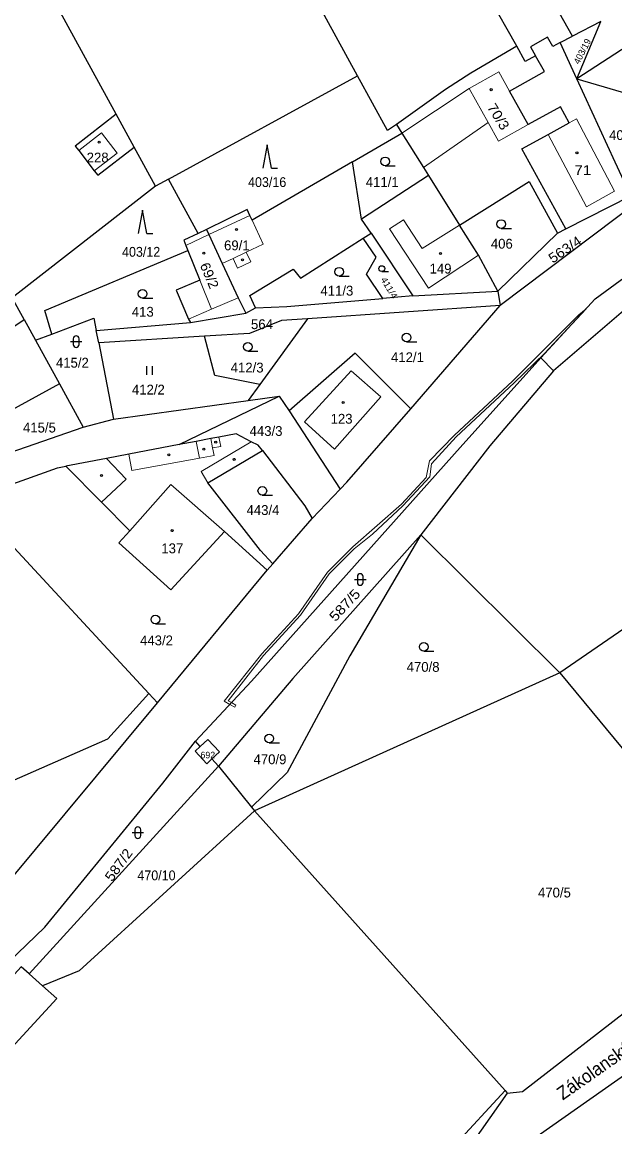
# Model space of a CAD drawing. Extents: x -754445 to -751443, y -1030748 to -1028224.
# Drawn here: x -753390.6 to -753288.1, y -1029073.5 to -1028882.4 of the extents above; entities that cross this region are included whole.
import ezdxf
from ezdxf.enums import TextEntityAlignment as Align

# ---------------------------------------------------------------- set-up
doc = ezdxf.new("R2010")
doc.units = 0
doc.header["$LTSCALE"] = 0.68
for name, color, linetype, lineweight in [('1', 7, 'Continuous', 25), ('13', 7, 'Continuous', 13), ('3', 7, 'Continuous', 25), ('4', 7, 'Continuous', 13), ('5', 7, 'Continuous', 25), ('7', 7, 'Continuous', 13)]:
    doc.layers.add(name, color=color, linetype=linetype, lineweight=lineweight)
doc.layers.add('2', color=7, linetype='Continuous')

msp = doc.modelspace()

# ---------------------------------------------------------------- linework, layer by layer
at = {"layer": '1'}
for p, q in [((-753305.08, -1028886.55), (-753326.53, -1028848.47)), ((-753365.3, -1028909.56), (-753332.6, -1028891.68)), ((-753371.22, -1028904), (-753374.33, -1028898.31)), ((-753333.5, -1028906.55), (-753324.95, -1028901.58)), ((-753367.52, -1028910.77), (-753371.22, -1028904)), ((-753320.35, -1028908.9), (-753331.91, -1028916.46)), ((-753358.73, -1028918.22), (-753360.18, -1028918.92)), ((-753308.36, -1028928.92), (-753298.03, -1028918.88)), ((-753390.28, -1028933.79), (-753392.33, -1028930.04)), ((-753323.03, -1028929.71), (-753328.26, -1028930.16)), ((-753308.36, -1028928.92), (-753307.94, -1028931.4)), ((-753377.78, -1028935.73), (-753361.49, -1028934.35)), ((-753377.37, -1028937.83), (-753377.78, -1028935.73)), ((-753300.94, -1028940.42), (-753298.71, -1028942.67)), ((-753384.17, -1028944.96), (-753401.72, -1028954.55)), ((-753363.45, -1028955.45), (-753346.15, -1028947.05)), ((-753380.08, -1028952.45), (-753374.79, -1028951.05)), ((-753344.46, -1028949.64), (-753335.62, -1028963.18)), ((-753347.27, -1028976.07), (-753340.47, -1028968.21)), ((-753321.68, -1028971.05), (-753297.62, -1028994.95)), ((-753297.62, -1028994.95), (-753350.45, -1029018.81)), ((-753356.65, -1029011.07), (-753357.8, -1029009.83)), ((-753356.65, -1029011.07), (-753389.38, -1029047.03)), ((-753356.65, -1029011.07), (-753350.96, -1029018.18)), ((-753387.07, -1029049.07), (-753389.38, -1029047.03)), ((-753307.09, -1029067.21), (-753306.72, -1029067.62))]:
    msp.add_line(p, q, dxfattribs=at)
for points in [[(-753332.6, -1028891.68), (-753349.38, -1028860.96), (-753357.68, -1028845.79), (-753366.13, -1028830.34)], [(-753297.57, -1028885.92), (-753295.46, -1028884.79), (-753318.45, -1028844.06), (-753326.53, -1028848.47)], [(-753374.33, -1028898.31), (-753392.6, -1028864.88), (-753403, -1028845.85)], [(-753294.67, -1028892.21), (-753290.53, -1028882.28), (-753295.46, -1028884.79)], [(-753281.53, -1028883.63), (-753294.67, -1028892.21), (-753262.81, -1028901.51)], [(-753305.08, -1028886.55), (-753313, -1028891.22), (-753317.41, -1028894.03), (-753325.9, -1028900.07), (-753324.95, -1028901.58)], [(-753301.83, -1028888.21), (-753303.61, -1028889.16), (-753305.08, -1028886.55)], [(-753297.57, -1028885.92), (-753298.85, -1028886.61), (-753299.76, -1028884.99), (-753302.71, -1028886.65), (-753301.83, -1028888.21)], [(-753288.04, -1028906.61), (-753294.67, -1028892.21), (-753297.57, -1028885.92)], [(-753296.61, -1028918.16), (-753304.19, -1028904.29), (-753299.62, -1028901.79), (-753296, -1028899.82), (-753297.54, -1028897), (-753303.08, -1028900.11), (-753306.33, -1028894.31), (-753300.29, -1028890.92), (-753301.83, -1028888.21)], [(-753325.9, -1028900.07), (-753327.42, -1028901.15), (-753332.6, -1028891.68)], [(-753245.48, -1028897.41), (-753261.79, -1028902.68), (-753275.92, -1028908.54), (-753283.86, -1028913.22), (-753307.94, -1028931.4)], [(-753374.33, -1028898.31), (-753381.43, -1028903.81), (-753380.82, -1028904.6), (-753378.13, -1028908.08), (-753377.52, -1028908.87), (-753371.22, -1028904)], [(-753324.95, -1028901.58), (-753321.22, -1028907.51), (-753320.35, -1028908.9), (-753314.95, -1028917.5)], [(-753333.5, -1028906.55), (-753350.85, -1028916.63), (-753351.24, -1028915.81), (-753351.71, -1028914.81), (-753358.73, -1028918.22)], [(-753331.63, -1028919.75), (-753330.28, -1028918.89), (-753331.91, -1028916.46), (-753333.5, -1028906.55)], [(-753296.61, -1028918.16), (-753285.35, -1028912.45), (-753288.04, -1028906.61)], [(-753360.18, -1028918.92), (-753365.3, -1028909.56), (-753367.52, -1028910.77), (-753392.33, -1028930.04)], [(-753314.95, -1028917.5), (-753302.91, -1028909.94), (-753298.03, -1028918.88), (-753296.61, -1028918.16)], [(-753360.18, -1028918.92), (-753362.67, -1028920.12), (-753362.31, -1028921.01), (-753361.96, -1028921.89)], [(-753358.73, -1028918.22), (-753358.31, -1028919.13), (-753356.01, -1028924.13), (-753353.28, -1028930.04), (-753351.91, -1028932.7), (-753350.24, -1028931.79)], [(-753330.28, -1028918.89), (-753323.03, -1028929.71), (-753308.36, -1028928.92)], [(-753308.36, -1028928.92), (-753311.68, -1028922.71), (-753314.95, -1028917.5)], [(-753350.24, -1028931.79), (-753351.21, -1028929.64), (-753343.72, -1028925.08), (-753342.46, -1028926.68), (-753331.63, -1028919.75)], [(-753350.24, -1028931.79), (-753344.82, -1028931.58), (-753328.26, -1028930.16), (-753331.07, -1028925.98), (-753329.41, -1028923.06), (-753331.63, -1028919.75)], [(-753233.79, -1028923.65), (-753232.06, -1028922.2), (-753233.74, -1028920.02), (-753236.01, -1028919.42), (-753256.01, -1028920.74), (-753278.94, -1028925.76), (-753298.71, -1028942.67)], [(-753385.5, -1028936.34), (-753386.69, -1028932.27), (-753361.96, -1028921.89)], [(-753361.96, -1028921.89), (-753359.9, -1028926.99), (-753363.98, -1028928.76), (-753361.83, -1028933.73), (-753361.49, -1028934.35), (-753351.91, -1028932.7)], [(-753300.94, -1028940.42), (-753291.49, -1028930.23), (-753282.22, -1028923.45)], [(-753323.4, -1028949.26), (-753307.94, -1028931.4), (-753341.29, -1028933.71), (-753349.53, -1028945.03), (-753351.55, -1028947.8), (-753346.15, -1028947.05), (-753344.46, -1028949.64)], [(-753408.77, -1028941.67), (-753399.03, -1028939.66), (-753390.28, -1028933.79)], [(-753390.28, -1028933.79), (-753388.3, -1028937.41), (-753385.5, -1028936.34)], [(-753385.5, -1028936.34), (-753378.2, -1028933.56), (-753377.78, -1028935.73)], [(-753341.29, -1028933.71), (-753345.74, -1028933.98), (-753351.27, -1028936.21), (-753359.09, -1028936.69)], [(-753388.3, -1028937.41), (-753384.17, -1028944.96), (-753380.08, -1028952.45)], [(-753349.53, -1028945.03), (-753357.28, -1028943.5), (-753359.09, -1028936.69), (-753377.37, -1028937.83)], [(-753377.37, -1028937.83), (-753374.79, -1028951.05), (-753351.55, -1028947.8)], [(-753323.4, -1028949.26), (-753333.03, -1028939.62), (-753344.46, -1028949.64)], [(-753360.62, -1029006.78), (-753350.96, -1028996.35), (-753314.84, -1028955.94), (-753300.94, -1028940.42)], [(-753298.71, -1028942.67), (-753309.75, -1028955.64), (-753321.68, -1028971.05)], [(-753335.62, -1028963.18), (-753334.45, -1028961.96), (-753323.4, -1028949.26)], [(-753464.67, -1028987.34), (-753448.8, -1028985.04), (-753428.33, -1028974.85), (-753396.89, -1028958.28), (-753380.08, -1028952.45)], [(-753349.07, -1028956.49), (-753349.78, -1028955.57), (-753350.98, -1028954.95), (-753353.6, -1028953.6), (-753356.57, -1028954.15), (-753357.99, -1028954.41), (-753360.49, -1028954.89), (-753363.45, -1028955.45)], [(-753363.45, -1028955.45), (-753372.13, -1028957.11), (-753376.03, -1028957.85), (-753383.05, -1028959.19)], [(-753347.27, -1028976.07), (-753349.37, -1028973.79), (-753358.5, -1028962.06), (-753349.07, -1028956.49)], [(-753349.07, -1028956.49), (-753341.72, -1028966.04), (-753340.47, -1028968.21), (-753335.62, -1028963.18)], [(-753394.88, -1028970.27), (-753399.83, -1028964.93), (-753384.52, -1028959.47), (-753383.05, -1028959.19)], [(-753383.05, -1028959.19), (-753376.87, -1028965.44), (-753372.01, -1028970.35), (-753373.87, -1028972.44), (-753364.88, -1028980.58), (-753355.61, -1028970.46), (-753348.23, -1028977.18), (-753347.27, -1028976.07)], [(-753400.1, -1029017), (-753375.78, -1029006.35), (-753368.71, -1028998.51), (-753394.88, -1028970.27)], [(-753321.68, -1028971.05), (-753343.79, -1028995.9), (-753356.65, -1029011.07)], [(-753321.68, -1028971.05), (-753333.97, -1028991.99), (-753344.8, -1029012.18), (-753350.96, -1029018.18), (-753350.45, -1029018.81)], [(-753368.71, -1028998.51), (-753367.2, -1029000.13), (-753348.23, -1028977.18)], [(-753282.89, -1028984.8), (-753297.62, -1028994.95), (-753266.4, -1029032.68)], [(-753419.48, -1029055.17), (-753408.84, -1029042.69), (-753393.71, -1029032.01), (-753367.2, -1029000.13)], [(-753429.75, -1029105.16), (-753421.74, -1029083.85), (-753416.16, -1029071.29), (-753408.48, -1029060.98), (-753399.35, -1029051.11), (-753386.69, -1029038.91), (-753366.27, -1029014.04), (-753360.62, -1029006.78)], [(-753357.8, -1029009.83), (-753358.69, -1029010.65), (-753360.69, -1029008.48), (-753359.8, -1029007.66), (-753360.62, -1029006.78)], [(-753357.8, -1029009.83), (-753356.48, -1029008.62), (-753358.48, -1029006.45), (-753359.8, -1029007.66)], [(-753350.45, -1029018.81), (-753380.72, -1029046.48), (-753387.07, -1029049.07)], [(-753369.62, -1029134.97), (-753307.09, -1029067.21), (-753350.45, -1029018.81)], [(-753239.27, -1029023.03), (-753276.34, -1029057.44), (-753301.53, -1029075.12), (-753321.63, -1029103.19)], [(-753306.72, -1029067.62), (-753304.1, -1029067.37), (-753283.84, -1029051.7), (-753266.4, -1029032.68)], [(-753389.38, -1029047.03), (-753390.8, -1029045.77), (-753407.74, -1029064.38), (-753407.08, -1029064.97)], [(-753387.07, -1029049.07), (-753384.63, -1029051.28), (-753401.69, -1029069.8), (-753407.08, -1029064.97)], [(-753306.72, -1029067.62), (-753331.11, -1029102.37), (-753369.62, -1029134.97)]]:
    msp.add_lwpolyline(points, dxfattribs=at)
at = {"layer": '13'}
for points in [[(-753355.67, -1028999.83), (-753354.7, -1029000.39), (-753354.43, -1029000.09), (-753354.98, -1028999.77), (-753348.85, -1028991.93), (-753342.5, -1028984.97), (-753337.52, -1028977.79), (-753333.18, -1028973.46), (-753330.03, -1028970.93), (-753324.75, -1028966.02), (-753320.12, -1028961.03), (-753319.82, -1028958.78), (-753315.55, -1028954.13), (-753305.52, -1028944.75), (-753300.26, -1028939.69), (-753293.09, -1028931.96), (-753294.36, -1028933), (-753305.8, -1028944.47), (-753315.83, -1028953.85), (-753320.16, -1028958.29), (-753320.77, -1028961.14), (-753325.03, -1028965.74), (-753333.44, -1028973.16), (-753337.82, -1028977.53), (-753342.82, -1028984.73), (-753349.15, -1028991.67)], [(-753353.65, -1029000.54), (-753354.43, -1029000.09), (-753354.7, -1029000.39), (-753353.84, -1029000.89)]]:
    msp.add_lwpolyline(points, close=True, dxfattribs=at)
at = {"layer": '3'}
for p, q in [((-753327.833, -1028907.21), (-753326.083, -1028907.21)), ((-753347.46, -1028907.61), (-753346.464, -1028907.61)), ((-753369.03, -1028918.93), (-753368.034, -1028918.93)), ((-753307.763, -1028918.05), (-753306.013, -1028918.05)), ((-753335.793, -1028926.3), (-753334.043, -1028926.3)), ((-753328.415, -1028925.52), (-753327.243, -1028925.52)), ((-753369.773, -1028930.11), (-753368.023, -1028930.11)), ((-753382.271, -1028937.631), (-753380.269, -1028937.631)), ((-753381.771, -1028937.131), (-753381.771, -1028938.132)), ((-753380.769, -1028938.132), (-753380.769, -1028937.131)), ((-753324.123, -1028937.67), (-753322.373, -1028937.67)), ((-753351.593, -1028939.29), (-753349.843, -1028939.29)), ((-753369.041, -1028943.38), (-753369.041, -1028941.88)), ((-753368.04, -1028943.38), (-753368.04, -1028941.88)), ((-753349.073, -1028964.2), (-753347.323, -1028964.2)), ((-753333.141, -1028978.791), (-753331.139, -1028978.791)), ((-753332.641, -1028978.291), (-753332.641, -1028979.292)), ((-753331.639, -1028979.292), (-753331.639, -1028978.291)), ((-753367.573, -1028986.47), (-753365.823, -1028986.47)), ((-753321.163, -1028991.2), (-753319.413, -1028991.2)), ((-753347.873, -1029007.05), (-753346.123, -1029007.05)), ((-753371.101, -1029022.081), (-753371.101, -1029023.082)), ((-753370.099, -1029023.082), (-753370.099, -1029022.081)), ((-753371.601, -1029022.581), (-753369.599, -1029022.581))]:
    msp.add_line(p, q, dxfattribs=at)
for points in [[(-753347.46, -1028907.61), (-753348.21, -1028903.61), (-753348.96, -1028907.61)], [(-753369.03, -1028918.93), (-753369.78, -1028914.93), (-753370.53, -1028918.93)]]:
    msp.add_lwpolyline(points, dxfattribs=at)
for centre, radius in [((-753327.8329, -1028906.4598), 0.75), ((-753307.7629, -1028917.2998), 0.75), ((-753328.4152, -1028925.0174), 0.5025), ((-753335.7929, -1028925.5498), 0.75), ((-753369.7729, -1028929.3598), 0.75), ((-753324.1229, -1028936.9198), 0.75), ((-753351.5929, -1028938.5398), 0.75), ((-753349.0729, -1028963.4498), 0.75), ((-753367.5729, -1028985.7198), 0.75), ((-753321.1629, -1028990.4498), 0.75), ((-753347.8729, -1029006.2998), 0.75)]:
    msp.add_circle(centre, radius, dxfattribs=at)
for centre, start, end in [((-753381.27, -1028937.1309), 0, 180), ((-753381.27, -1028938.1309), 180, 359.98789), ((-753332.14, -1028978.2909), 0, 180), ((-753332.14, -1028979.2909), 180, 359.98789), ((-753370.6, -1029022.0809), 0, 180), ((-753370.6, -1029023.0809), 180, 359.98789)]:
    msp.add_arc(centre, 0.5, start, end, dxfattribs=at)
at = {"layer": '4'}
for p, q in [((-753308.19, -1028890.99), (-753313.33, -1028893.87)), ((-753308.19, -1028890.99), (-753306.33, -1028894.31)), ((-753313.33, -1028893.87), (-753324.95, -1028901.58)), ((-753313.33, -1028893.87), (-753310.03, -1028899.76)), ((-753310.03, -1028899.76), (-753321.22, -1028907.51)), ((-753310.03, -1028899.76), (-753308.22, -1028902.99)), ((-753296, -1028899.82), (-753294.75, -1028899.13)), ((-753294.75, -1028899.13), (-753288.17, -1028911.64)), ((-753380.82, -1028904.6), (-753376.87, -1028901.54)), ((-753374.18, -1028905.02), (-753376.87, -1028901.54)), ((-753308.22, -1028902.99), (-753303.08, -1028900.11)), ((-753299.62, -1028901.79), (-753293.04, -1028914.3)), ((-753378.13, -1028908.08), (-753374.18, -1028905.02)), ((-753293.04, -1028914.3), (-753288.17, -1028911.64)), ((-753358.31, -1028919.13), (-753351.24, -1028915.81)), ((-753350.85, -1028916.63), (-753348.9, -1028920.79)), ((-753324.68, -1028916.58), (-753327.07, -1028918.14)), ((-753321.42, -1028921.56), (-753324.68, -1028916.58)), ((-753327.07, -1028918.14), (-753320.36, -1028928.39)), ((-753321.42, -1028921.56), (-753314.95, -1028917.5)), ((-753362.31, -1028921.01), (-753358.31, -1028919.13)), ((-753348.9, -1028920.79), (-753351.84, -1028922.17)), ((-753351.84, -1028922.17), (-753354.14, -1028923.25)), ((-753351.84, -1028922.17), (-753351.05, -1028923.85)), ((-753320.36, -1028928.39), (-753311.68, -1028922.71)), ((-753354.14, -1028923.25), (-753356.01, -1028924.13)), ((-753354.14, -1028923.25), (-753353.36, -1028924.91)), ((-753351.05, -1028923.85), (-753353.36, -1028924.91)), ((-753357.87, -1028932.02), (-753359.9, -1028926.99)), ((-753357.87, -1028932.02), (-753353.28, -1028930.04)), ((-753361.83, -1028933.73), (-753357.87, -1028932.02)), ((-753333.7, -1028942.67), (-753341.78, -1028951.49)), ((-753333.7, -1028942.67), (-753328.6, -1028947.19)), ((-753328.6, -1028947.19), (-753336.61, -1028956.23)), ((-753336.61, -1028956.23), (-753341.78, -1028951.49)), ((-753359.93, -1028957.81), (-753360.49, -1028954.89)), ((-753359.67, -1028960.08), (-753350.98, -1028954.95)), ((-753357.68, -1028956.03), (-753357.99, -1028954.41)), ((-753356.27, -1028955.77), (-753356.57, -1028954.15)), ((-753372.13, -1028957.11), (-753371.62, -1028959.93)), ((-753357.68, -1028956.03), (-753356.27, -1028955.77)), ((-753357.43, -1028957.36), (-753357.68, -1028956.03)), ((-753376.03, -1028957.85), (-753372.64, -1028961.41)), ((-753371.62, -1028959.93), (-753359.93, -1028957.81)), ((-753359.93, -1028957.81), (-753357.43, -1028957.36)), ((-753358.5, -1028962.06), (-753359.67, -1028960.08)), ((-753376.87, -1028965.44), (-753372.64, -1028961.41)), ((-753372.01, -1028970.35), (-753364.89, -1028962.33)), ((-753364.89, -1028962.33), (-753355.61, -1028970.46))]:
    msp.add_line(p, q, dxfattribs=at)
at = {"layer": '5'}
for centre in [(-753309.5068, -1028894.0592), (-753377.3068, -1028903.1292), (-753294.6668, -1028904.9992), (-753353.5368, -1028918.2592), (-753359.1768, -1028922.3392), (-753318.2668, -1028922.3892), (-753352.5068, -1028923.4992), (-753335.0968, -1028948.1892), (-753357.1368, -1028955.0492), (-753365.2468, -1028957.2092), (-753359.1868, -1028956.2392), (-753353.9468, -1028958.0092), (-753376.8668, -1028960.7992), (-753364.6468, -1028970.3392)]:
    msp.add_circle(centre, 0.175, dxfattribs=at)

# ---------------------------------------------------------------- texts
at = {"layer": '2'}
msp.add_text('403/19', height=1.14, rotation=63, dxfattribs=at).set_placement((-753293.2437, -1028887.6853), align=Align.CENTER)
for s, height, rotation, width, p in [('70/3', 1.7, 302, 1.1, (-753308.9726, -1028899.1701)), ('563/4', 1.7, 34, 1.1, (-753296.2668, -1028922.4104)), ('69/2', 1.7, 293, 1.05, (-753359.0083, -1028926.5534)), ('411/4', 1.14, 301, 1.05, (-753327.6105, -1028928.6289)), ('587/5', 1.7, 47, 1.15, (-753334.2072, -1028983.8032)), ('587/2', 1.7, 54, 1.1, (-753373.2301, -1029028.6566))]:
    msp.add_text(s, height=height, rotation=rotation, dxfattribs=dict(at, width=width)).set_placement(p, align=Align.CENTER)
for s, height, p in [('402/2', 1.7, (-753286.26, -1028902.77)), ('228', 1.7, (-753377.549, -1028906.65)), ('411/1', 1.7, (-753328.34, -1028910.89)), ('69/1', 1.7, (-753353.48, -1028921.84)), ('406', 1.7, (-753307.659, -1028921.56)), ('149', 1.7, (-753318.259, -1028925.86)), ('411/3', 1.7, (-753336.18, -1028929.68)), ('413', 1.7, (-753369.749, -1028933.33)), ('564', 1.7, (-753349.139, -1028935.48)), ('412/1', 1.7, (-753323.98, -1028941.19)), ('415/2', 1.7, (-753381.92, -1028942.14)), ('412/3', 1.7, (-753351.7, -1028942.98)), ('412/2', 1.7, (-753368.78, -1028946.79)), ('123', 1.7, (-753335.369, -1028951.84)), ('415/5', 1.7, (-753387.62, -1028953.36)), ('443/3', 1.7, (-753348.43, -1028953.95)), ('443/4', 1.7, (-753348.96, -1028967.63)), ('137', 1.7, (-753364.639, -1028974.25)), ('443/2', 1.7, (-753367.37, -1028990.18)), ('470/8', 1.7, (-753321.27, -1028994.76)), ('692', 1.14, (-753358.5, -1029009.73)), ('470/9', 1.7, (-753347.75, -1029010.74)), ('470/5', 1.7, (-753298.56, -1029033.79))]:
    msp.add_text(s, height=height, dxfattribs=at).set_placement(p, align=Align.CENTER)
for s, width, p in [('71', 1.15, (-753293.65, -1028908.83)), ('403/16', 0.95, (-753348.239, -1028910.9)), ('403/12', 0.95, (-753370.029, -1028922.96)), ('470/10', 0.95, (-753367.379, -1029030.82))]:
    msp.add_text(s, height=1.7, dxfattribs=dict(at, width=width)).set_placement(p, align=Align.CENTER)
at = {"layer": '7', "width": 0.95}
msp.add_text('Zákolanský potok', height=2.3, rotation=35, dxfattribs=at).set_placement((-753287.8006, -1029062.412), align=Align.CENTER)

doc.saveas('drawing.dxf')
